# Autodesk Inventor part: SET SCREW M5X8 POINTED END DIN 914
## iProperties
IsCustomPart: 1
Created: 2006-02
Part Number: SET SCREW M5X8 POINTED END DIN 914
Material: Steel, Mild
Description: Hexagon Socket Set Screw
Document SubType Name: Modeling
Standard: DIN 914
Designer: Andy Moles
Standards Organization: DIN
Language: en-US
Size Designation: M5 x 8
Categories: <MemberInstance><Categories><Category DisplayName="Fasteners" InternalName="e4da775c-781d-43d5-af7c-5136215cf5a6" Mnemonic="FSTN"><Category DisplayName="Bolts"
Density: 1 g/cm^3
Author: Andy Moles
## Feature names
1. Body [Revolution]
2. Slot [Extrusion]
3. Chamfer1
4. Chamfer2
